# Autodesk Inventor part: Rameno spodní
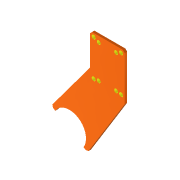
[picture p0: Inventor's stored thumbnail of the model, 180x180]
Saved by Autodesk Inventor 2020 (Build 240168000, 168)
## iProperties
Created: 2025-03
Part Number: Rameno spodní
Material: Ocel
Document SubType Name: Modeling
Designer: doma
Density: 7.85 g/cm^3
Appearance: Hladká – světle oranžová
Mass: 3299.55 g
Surface Area: 980.95 cm^2
Volume: 420.325 cm^3
Author: doma
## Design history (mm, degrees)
sketch "Náčrt1"
  geometry: L1 (3887.119, 474.261)-(3887.119, 547.261); L2 (3887.119, 474.261)-(3887.119, 444.062); L3 (4007.119, 394.261)-(4007.119, 547.261); L4 (4000.119, 554.261)-(3894.119, 554.261); L5 (4007.119, 547.261)-(4000.119, 554.261); L6 (3887.119, 547.261)-(3894.119, 554.261); L7 (4007.119, 394.261)-(3881.944, 191.421); L8 (3872.351, 189.206)-(3864.48, 194.064); L9 (3887.119, 444.062)-(3756.682, 268.243); L10 (3758.743, 259.315)-(3756.682, 268.243); L11 (3872.351, 189.206)-(3881.944, 191.421); L12 (3766.615, 254.458)-(3758.743, 259.315); A1 r 57.5 centre (3815.547, 224.261) between (3864.48, 194.064) and (3766.615, 254.458); 13 further points
  constraints: 24 end point, 2 point on circle, 1 centre point
extrude "Vysunutí1" new body sketch "Náčrt1" distance "d54" = 10; taper "d55" = 0 deg
sketch "Náčrt2" dims "d63" = 10, "d70" = 10
  geometry: L1 (-4007.119, 394.261)-(-4007.119, 547.261) reference; L2 (-4000.119, 554.261)-(-3894.119, 554.261) reference; 5 further points
  constraints: 1 horizontal, 1 vertical, 3 other
  dimensions: "d56" = 30 distance from line of L1 point (-3977.119, 534.261); "d57" = 20 distance from line of L2 point (-3977.119, 534.261); "d60" = 60 distance of point (-3977.119, 534.261) point (-3917.119, 534.261); "d67" = 115 distance of point (-3977.119, 534.261) point (-3977.119, 419.261)
hole "Díra1" sketch "Náčrt2" at (-3977.119, 534.261), (-3917.119, 534.261), (-3977.119, 419.261), (-3917.119, 419.261) diameter "d72" = 13.5; stored, may be unused: countersink angle "d76" = 90 deg, drill point angle "d78" = 118 deg; dims "d73" = 6, "d74" = 4, "d75" = 2, "d77" = 8
sketch "Náčrt3"
  geometry: C1 r 5.053 at (3899.619, 541.761) reference; C2 r 5.053 at (3994.619, 541.761) reference; C3 r 6.75 at (3994.619, 416.761) reference; C4 r 5.053 at (3899.619, 416.761) reference; 5 further points
  constraints: 4 coincident
hole "Díra2" sketch "Náčrt3" at (3899.619, 416.761), (3899.619, 541.761), (3994.619, 541.761), (3994.619, 416.761) diameter "d79" = 14; stored, may be unused: countersink angle "d83" = 90 deg, drill point angle "d85" = 118 deg; dims "d80" = 24, "d81" = 4, "d82" = 2, "d84" = 8
chamfer "Zkosení1" distance "d86" = 2; stored, may be unused: second distance "d87" = 2, angle "d88" = 45 deg
chamfer "Zkosení2" distance "d89" = 2; stored, may be unused: second distance "d90" = 2, angle "d91" = 45 deg
node "Těleso1"
node "Referenční1"
node "Referenční2"
node "Referenční3"
node "Referenční4"
